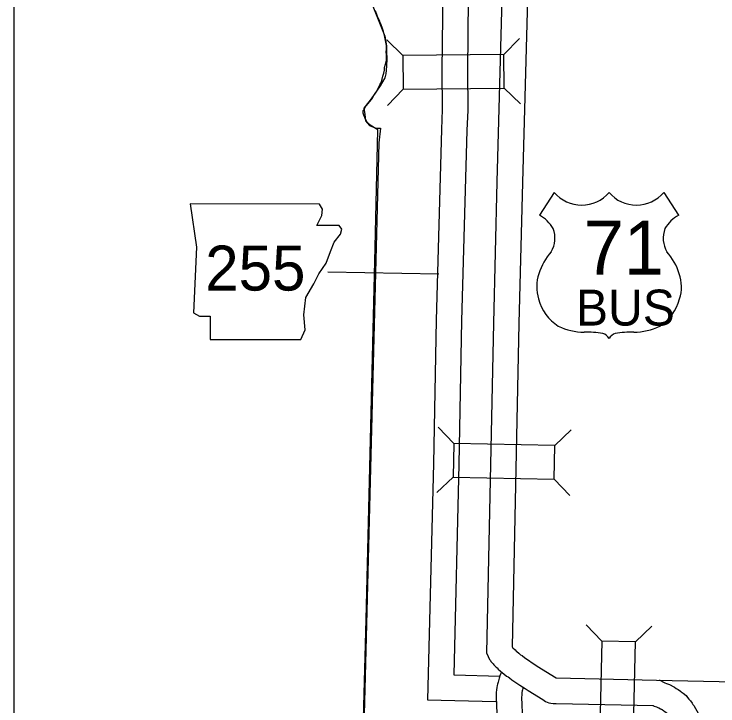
# Model space of a CAD drawing. Extents: x 1370567 to 1373900, y 377514 to 379648.
# Drawn here: x 1370727.3 to 1370810, y 379384.9 to 379466.1 of the extents above; entities that cross this region are included whole.
import ezdxf

# ---------------------------------------------------------------- set-up
doc = ezdxf.new("R2010")
doc.units = 0
doc.layers.add('Default', color=7, linetype='Continuous')
doc.layers.add('Survey Symbols', color=7, linetype='Continuous')

msp = doc.modelspace()

# ---------------------------------------------------------------- linework, layer by layer
at = {"layer": 'Default'}
for p, q in [((1370772.936, 379461.248), (1370771.048, 379463.093)), ((1370784.816, 379461.389), (1370786.66, 379463.277)), ((1370772.983, 379457.289), (1370771.139, 379455.4)), ((1370784.862, 379457.429), (1370786.751, 379455.584)), ((1370790.736, 379445.186), (1370789.005, 379442.509)), ((1370803.605, 379445.186), (1370805.336, 379442.509)), ((1370764.114, 379435.832), (1370777.183, 379435.602)), ((1370778.933, 379415.697), (1370777.107, 379417.603)), ((1370790.811, 379415.445), (1370792.717, 379417.272)), ((1370778.849, 379411.738), (1370776.943, 379409.911)), ((1370790.727, 379411.486), (1370792.553, 379409.58)), ((1370796.315, 379392.476), (1370794.489, 379394.382)), ((1370800.275, 379392.391), (1370802.181, 379394.218))]:
    msp.add_line(p, q, dxfattribs=at)
for points in [[(1370777.668, 379472.225), (1370777.528, 379459.508), (1370777.583, 379454.908), (1370777.473, 379452.553), (1370776.848, 379430.173), (1370776.528, 379413.332), (1370775.854, 379385.586), (1370783.872, 379385.363)], [(1370780.667, 379472.192), (1370780.528, 379459.509), (1370780.584, 379454.856), (1370780.471, 379452.441), (1370779.847, 379430.103), (1370779.527, 379413.267), (1370778.926, 379388.502), (1370784.394, 379388.35)], [(1370784.688, 379472.275), (1370783.995, 379446.428), (1370783.582, 379429.835), (1370782.761, 379391.109), (1370782.977, 379390.658), (1370783.025, 379390.549), (1370783.175, 379390.279), (1370783.231, 379390.201), (1370783.297, 379390.085), (1370783.467, 379389.871), (1370783.538, 379389.792), (1370783.623, 379389.685), (1370783.891, 379389.401), (1370784.014, 379389.311), (1370784.144, 379389.165), (1370784.407, 379388.937), (1370784.658, 379388.732), (1370784.81, 379388.604), (1370785.131, 379388.352), (1370785.302, 379388.26), (1370785.458, 379388.134), (1370785.74, 379387.929), (1370786.696, 379387.278), (1370787.299, 379386.885), (1370787.666, 379386.659), (1370789.385, 379385.596), (1370789.685, 379385.39), (1370790.08, 379385.225), (1370790.325, 379385.167), (1370790.589, 379385.136), (1370790.732, 379385.138), (1370790.87, 379385.14), (1370790.956, 379385.148), (1370802.395, 379384.904)], [(1370787.687, 379472.194), (1370786.994, 379446.35), (1370786.582, 379429.766), (1370785.776, 379391.795), (1370785.784, 379391.78), (1370785.833, 379391.725), (1370785.878, 379391.67), (1370786.132, 379391.445), (1370786.258, 379391.302), (1370786.338, 379391.233), (1370786.572, 379391.043), (1370786.701, 379390.934), (1370786.784, 379390.869), (1370786.975, 379390.765), (1370787.283, 379390.516), (1370787.464, 379390.385), (1370788.36, 379389.774), (1370788.904, 379389.419), (1370789.241, 379389.212), (1370790.96, 379388.149), (1370802.754, 379387.897)], [(1370768.53, 379469.386), (1370770.045, 379465.5), (1370770.814, 379463.541), (1370771.013, 379462.416), (1370771.042, 379461.658), (1370771.07, 379460.901), (1370771.005, 379460.006), (1370770.94, 379459.111), (1370770.823, 379458.643), (1370770.267, 379457.713), (1370769.209, 379456.187)], [(1370768.241, 379380.445), (1370768.628, 379395.021), (1370768.994, 379409.666), (1370769.678, 379438.726), (1370770.014, 379452.53), (1370769.119, 379453.071), (1370768.887, 379453.259), (1370768.796, 379453.378), (1370768.715, 379453.478), (1370768.623, 379453.647), (1370768.521, 379453.846), (1370768.479, 379453.976), (1370768.407, 379454.125), (1370768.366, 379454.235), (1370768.325, 379454.365), (1370768.293, 379454.475), (1370768.282, 379454.575), (1370768.281, 379454.695), (1370768.3, 379454.785), (1370768.339, 379454.846), (1370768.388, 379454.926), (1370768.437, 379455.017), (1370768.593, 379455.299), (1370768.682, 379455.39), (1370768.859, 379455.622), (1370769.037, 379455.805), (1370769.243, 379456.087), (1370769.381, 379456.269), (1370769.537, 379456.551), (1370769.665, 379456.713), (1370769.812, 379456.975), (1370769.997, 379457.317), (1370770.134, 379457.569), (1370770.251, 379457.801), (1370770.368, 379458.022), (1370770.446, 379458.203), (1370770.523, 379458.465), (1370770.609, 379458.816), (1370770.714, 379459.178), (1370770.79, 379459.559), (1370770.806, 379459.84), (1370770.921, 379460.262), (1370771.016, 379460.683), (1370771.033, 379460.914), (1370771.018, 379461.344), (1370770.984, 379461.674), (1370771.01, 379462.035), (1370771.005, 379462.456), (1370770.961, 379462.826), (1370770.886, 379463.236), (1370770.801, 379463.625), (1370770.686, 379464.065), (1370770.521, 379464.564), (1370770.397, 379464.873), (1370770.294, 379465.132), (1370770.232, 379465.311), (1370770.17, 379465.471), (1370770.048, 379465.69), (1370769.986, 379465.85), (1370769.749, 379466.508)], [(1370769.209, 379456.187), (1370768.373, 379455.087), (1370768.467, 379454.345), (1370768.561, 379453.603), (1370769.026, 379453.03), (1370769.76, 379452.708), (1370770.307, 379452.728), (1370770.137, 379450.994), (1370768.464, 379386.82), (1370767.543, 379351.503)], [(1370784.514, 379388.844), (1370784.481, 379388.759), (1370784.42, 379388.591), (1370784.337, 379388.375), (1370784.244, 379388.097), (1370784.166, 379387.804), (1370784.124, 379387.652), (1370784.064, 379387.412), (1370784.031, 379387.247), (1370783.984, 379387.026), (1370783.93, 379386.758), (1370783.918, 379386.437), (1370783.909, 379386.224), (1370783.902, 379385.868), (1370784.007, 379383.015)], [(1370802.754, 379387.897), (1370835.819, 379387.193)], [(1370803.06, 379387.906), (1370803.738, 379387.566), (1370803.901, 379387.498), (1370804.018, 379387.45), (1370804.267, 379387.355), (1370804.491, 379387.235), (1370804.534, 379387.217), (1370804.86, 379387.058), (1370805.071, 379386.911), (1370805.281, 379386.777), (1370805.549, 379386.584), (1370805.641, 379386.508), (1370805.862, 379386.37), (1370806.211, 379386.081), (1370806.376, 379385.858), (1370806.536, 379385.665), (1370806.588, 379385.598), (1370806.734, 379385.455), (1370806.946, 379385.17), (1370807.026, 379385.025), (1370807.112, 379384.903), (1370808.418, 379382.596)], [(1370787.073, 379387.063), (1370787.062, 379387.024), (1370787.027, 379386.894), (1370786.992, 379386.752), (1370786.968, 379386.637), (1370786.921, 379386.416), (1370786.918, 379386.403), (1370786.915, 379386.323), (1370786.908, 379386.135), (1370786.903, 379385.891), (1370787.004, 379383.138)], [(1370802.329, 379384.917), (1370802.488, 379384.837), (1370802.747, 379384.729), (1370802.911, 379384.661), (1370803.022, 379384.619), (1370803.201, 379384.523), (1370803.298, 379384.482), (1370803.334, 379384.465), (1370803.405, 379384.415), (1370803.597, 379384.293), (1370803.712, 379384.21), (1370803.882, 379384.069), (1370804.049, 379383.965), (1370804.199, 379383.783), (1370804.349, 379383.592), (1370804.401, 379383.542), (1370804.576, 379383.294), (1370805.807, 379381.118)]]:
    msp.add_lwpolyline(points, dxfattribs=at)
for points in [[(1370784.816, 379461.389), (1370772.936, 379461.248), (1370772.983, 379457.289), (1370784.862, 379457.429)], [(1370747.948, 379443.822), (1370748.709, 379438.747), (1370748.371, 379431.049), (1370749.048, 379430.626), (1370750.316, 379430.626), (1370750.316, 379427.919), (1370760.975, 379427.919), (1370761.482, 379429.019), (1370761.313, 379430.795), (1370761.567, 379432.826), (1370762.497, 379434.433), (1370763.089, 379435.617), (1370763.935, 379436.886), (1370764.443, 379438.239), (1370764.866, 379439.339), (1370765.627, 379440.27), (1370765.796, 379440.862), (1370765.458, 379441.285), (1370762.836, 379441.285), (1370763.428, 379442.469), (1370763.512, 379443.23), (1370763.162, 379443.815)], [(1370790.811, 379415.445), (1370778.933, 379415.697), (1370778.849, 379411.738), (1370790.727, 379411.486)], [(1370796.315, 379392.476), (1370796.062, 379380.598), (1370800.021, 379380.514), (1370800.275, 379392.391)]]:
    msp.add_lwpolyline(points, close=True, dxfattribs=at)
for centre, radius, start, end in [((1370793.959, 379447.898), 4.212, 220.07504, 319.67012), ((1370800.382, 379447.898), 4.212, 220.32988, 319.92496), ((1370786.744, 379438.624), 4.497, 30.7809, 59.98827), ((1370807.598, 379438.624), 4.497, 120.01173, 149.2191), ((1370787.733, 379439.81), 3.083, 328.81046, 21.21077), ((1370806.608, 379439.81), 3.083, 158.78923, 211.18954), ((1370795.794, 379433.491), 7.192, 138.95648, 162.69135), ((1370798.547, 379433.491), 7.192, 17.30865, 41.04352), ((1370793.42, 379434.08), 4.752, 160.95764, 197.38186), ((1370800.921, 379434.08), 4.752, 342.61814, 19.04236), ((1370794.194, 379434.094), 5.498, 195.10743, 237.13119), ((1370800.148, 379434.094), 5.498, 302.86881, 344.89257), ((1370794.296, 379435.825), 7.06, 244.07708, 269.57785), ((1370794.459, 379415.834), 12.933, 81.19416, 90.95387), ((1370799.882, 379415.834), 12.933, 89.04613, 98.80584), ((1370800.045, 379435.825), 7.06, 270.42215, 295.92292), ((1370796.077, 379427.429), 1.239, 28.03422, 72.98637), ((1370798.265, 379427.429), 1.239, 107.01363, 151.96578)]:
    msp.add_arc(centre, radius, start, end, dxfattribs=at)
at = {"layer": 'Survey Symbols'}
msp.add_lwpolyline([(1370727.274, 379552.541), (1371456.671, 379552.541), (1371456.671, 378768.055), (1370727.274, 378768.055)], close=True, dxfattribs=at)
msp.add_lwpolyline([(1370727.274, 379552.541), (1371456.671, 379552.541), (1371456.671, 378768.055), (1370727.274, 378768.055)], close=True, dxfattribs=at)
msp.add_lwpolyline([(1370727.274, 379552.541), (1371456.671, 379552.541), (1371456.671, 378768.055), (1370727.274, 378768.055)], close=True, dxfattribs=at)
msp.add_lwpolyline([(1370727.274, 379552.541), (1371456.671, 379552.541), (1371456.671, 378768.055), (1370727.274, 378768.055)], close=True, dxfattribs=at)
msp.add_lwpolyline([(1370727.274, 379552.541), (1371456.671, 379552.541), (1371456.671, 378768.055), (1370727.274, 378768.055)], close=True, dxfattribs=at)
msp.add_lwpolyline([(1370727.274, 379552.541), (1371456.671, 379552.541), (1371456.671, 378768.055), (1370727.274, 378768.055)], close=True, dxfattribs=at)

# ---------------------------------------------------------------- texts
at = {"layer": 'Default'}
for s, height, p in [('71', 6.336, (1370794.196, 379435.533)), ('255', 5.28, (1370749.726, 379433.65)), ('BUS', 4.224, (1370793.283, 379429.534))]:
    msp.add_text(s, height=height, dxfattribs=at).set_placement(p)

doc.saveas('drawing.dxf')
